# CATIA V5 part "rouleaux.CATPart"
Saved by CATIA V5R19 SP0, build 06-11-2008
Part number: Part5
Bounding box of the stored display mesh (mm): x -49.986 to 49.986, y -15 to 15, z -49.986 to 49.986
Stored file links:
  F:\20\rouleaux.CATPart
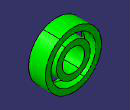
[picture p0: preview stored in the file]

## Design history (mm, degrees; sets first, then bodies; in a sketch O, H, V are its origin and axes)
Body1 (main body)
  Sketch1 on yz-plane, origin (0, 0, 0), H (0, 1, 0), V (0, 0, 1)
    line L1 (-15, 50) -> (-15, 45)
    line L2 (-15, 45) -> (-5, 45)
    line L3 (-5, 45) -> (-5, 40)
    line L4 (-5, 40) -> (15, 40)
    line L5 (15, 40) -> (15, 50)
    line L6 (15, 50) -> (-15, 50)
    line L7 (-15, 30) -> (15, 30)
    line L8 (15, 30) -> (15, 20)
    line L9 (15, 20) -> (-15, 20)
    line L10 (-15, 20) -> (-15, 30)
    length L6 = 30
    length L1 = 5
    length L5 = 10
    length L4 = 20
    distance L4 H = 40
    length L9 = 30
    length L8 = 10
    distance L9 H = 20
    vertical: L1 V, L3 V, L5 V, L8 V, L10 V
    horizontal: L2 H, L4 H, L6 H, L7 H, L9 H
    coincidence: L1 L10
    symmetry: L1 L5 V
  Shaft1: profile Sketch1, axis Sketch1.H, angle 360
  Point1: type Center, Curve edge [face of Shaft1 from Sketch1.L9 | face of Shaft1 from Sketch1.L10]
  Line1: type Normal, RefSkin face of Shaft1 from Sketch1.L10, Start 0, End 20, RefPoint Point1
  Plane1: type Offset, Offset 0, RefPlane zx-plane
